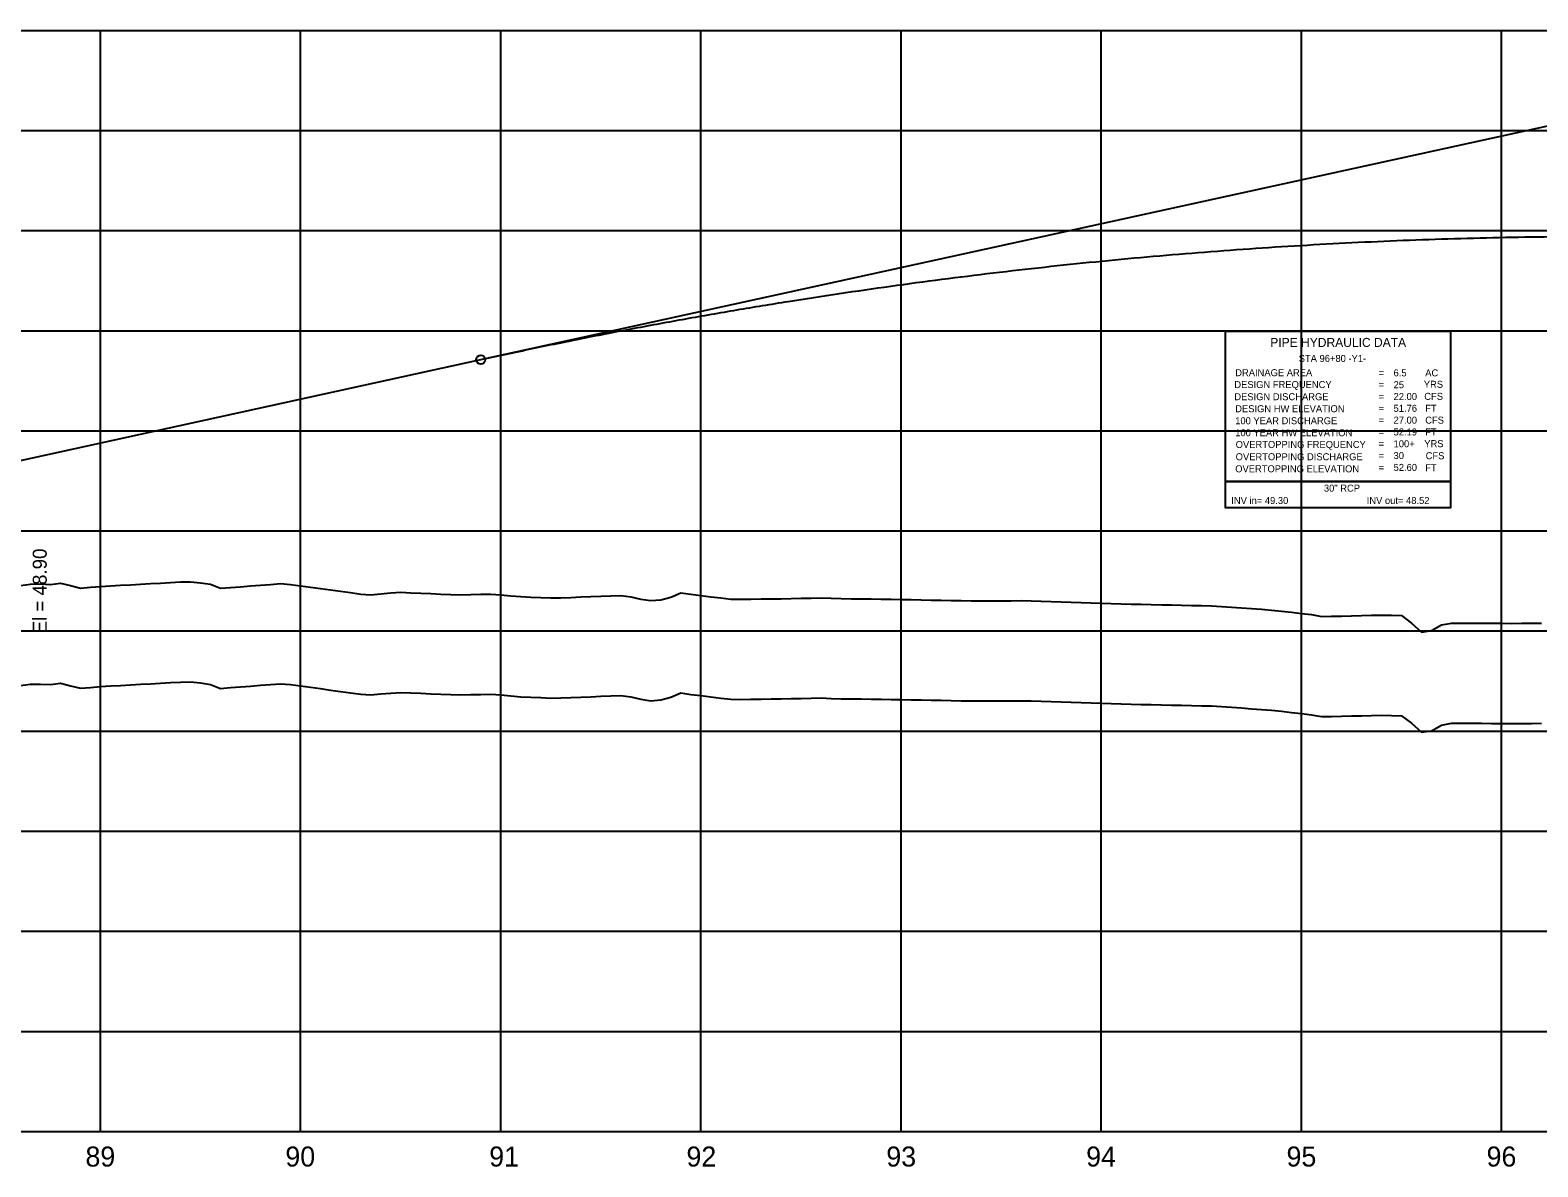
# Model space of a CAD drawing. Extents: x 2345490 to 2436403, y 465165 to 573888.
# Drawn here: x 2389186 to 2389940, y 557766 to 558334 of the extents above; entities that cross this region are included whole.
import ezdxf

# ---------------------------------------------------------------- set-up
doc = ezdxf.new("R2010")
doc.units = 0
for name, color, linetype in [('Old_Level_1', 7, 'Continuous'), ('Old_Level_2', 7, 'Continuous'), ('Old_Level_3', 7, 'Continuous'), ('Old_Level_4', 7, 'Continuous'), ('Old_Level_57', 7, 'Continuous'), ('Old_Level_62', 7, 'Continuous'), ('Old_Level_63', 7, 'Continuous')]:
    doc.layers.add(name, color=color, linetype=linetype)

msp = doc.modelspace()

# ---------------------------------------------------------------- linework, layer by layer
at = {"layer": 'Old_Level_1'}
for points in [[(2389181.5425, 558006.83375), (2389186.5425, 558007.4795), (2389191.5425, 558007.60325), (2389196.5425, 558007.32175), (2389201.5425, 558007.987), (2389206.5425, 558006.761), (2389211.5425, 558005.56825), (2389216.5425, 558005.94675), (2389221.5425, 558006.32525), (2389226.5425, 558006.6745), (2389231.5425, 558006.94825), (2389236.5425, 558007.222), (2389241.5425, 558007.49575), (2389246.5425, 558007.7695), (2389251.5425, 558008.04325), (2389256.5425, 558008.317), (2389261.5425, 558008.58825), (2389266.5425, 558008.64375), (2389271.5425, 558008.23575), (2389276.5425, 558007.4265), (2389281.5425, 558005.44875), (2389286.5425, 558005.836), (2389291.5425, 558006.22325), (2389296.5425, 558006.6105), (2389301.5425, 558006.99775), (2389306.5425, 558007.3845), (2389311.5425, 558007.765), (2389316.5425, 558007.39975), (2389321.5425, 558006.70825)], [(2389321.5425, 558006.70825), (2389326.5425, 558006.01675), (2389331.5425, 558005.32525), (2389336.5425, 558004.63375), (2389341.5425, 558003.942), (2389346.5425, 558003.2505), (2389351.5425, 558002.559), (2389356.5425, 558002.23), (2389361.5425, 558002.66475), (2389366.5425, 558003.0995), (2389371.5425, 558003.452), (2389376.5425, 558003.224), (2389381.5425, 558002.99575), (2389386.5425, 558002.7675), (2389391.5425, 558002.5395), (2389396.5425, 558002.31125), (2389401.5425, 558002.15925), (2389406.5425, 558002.37775), (2389411.5425, 558002.449), (2389416.5425, 558002.52025), (2389421.5425, 558002.22925), (2389426.5425, 558001.71875), (2389431.5425, 558001.29225), (2389436.5425, 558001.06275), (2389441.5425, 558000.8335), (2389446.5425, 558000.604), (2389451.5425, 558000.64475), (2389456.5425, 558000.89975), (2389461.5425, 558001.09525), (2389466.5425, 558001.291), (2389471.5425, 558001.4865), (2389476.5425, 558001.682), (2389481.5425, 558001.87775), (2389486.5425, 558001.20975), (2389491.5425, 557999.98425), (2389496.5425, 557999.304), (2389501.5425, 557999.6535), (2389506.5425, 558001.0615), (2389511.5425, 558003.237), (2389516.5425, 558002.43), (2389521.5425, 558001.827), (2389526.5425, 558001.22375), (2389531.5425, 558000.62075), (2389536.5425, 558000.0175), (2389541.5425, 557999.96125), (2389546.5425, 558000.05), (2389551.5425, 558000.11375), (2389556.5425, 558000.1775), (2389561.5425, 558000.2415), (2389566.5425, 558000.3385), (2389571.5425, 558000.453), (2389576.5425, 558000.5675), (2389581.5425, 558000.67825), (2389586.5425, 558000.446), (2389591.5425, 558000.2805), (2389596.5425, 558000.238), (2389601.5425, 558000.1955), (2389606.5425, 558000.11675), (2389611.5425, 558000.02675), (2389616.5425, 557999.937), (2389621.5425, 557999.847), (2389626.5425, 557999.757), (2389631.5425, 557999.667), (2389636.5425, 557999.577), (2389641.5425, 557999.487), (2389646.5425, 557999.397), (2389651.5425, 557999.307), (2389656.5425, 557999.217), (2389661.5425, 557999.226), (2389666.5425, 557999.23525), (2389671.5425, 557999.2445), (2389676.5425, 557999.25375), (2389681.5425, 557999.263), (2389686.5425, 557999.17775), (2389691.5425, 557999.00875), (2389696.5425, 557998.83975), (2389701.5425, 557998.67075), (2389706.5425, 557998.50175), (2389711.5425, 557998.33275), (2389716.5425, 557998.16375), (2389721.5425, 557997.99475), (2389726.5425, 557997.82575), (2389731.5425, 557997.66125), (2389736.5425, 557997.548), (2389741.5425, 557997.4365), (2389746.5425, 557997.325), (2389751.5425, 557997.21375), (2389756.5425, 557997.10225), (2389761.5425, 557996.99075), (2389766.5425, 557996.8795), (2389771.5425, 557996.768), (2389776.5425, 557996.65675), (2389781.5425, 557996.39), (2389786.5425, 557996.02925), (2389791.5425, 557995.6685), (2389796.5425, 557995.30775), (2389801.5425, 557994.947), (2389806.5425, 557994.58625), (2389811.5425, 557994.03675), (2389816.5425, 557993.48175), (2389821.5425, 557992.92675)], [(2389821.5425, 557992.92675), (2389826.5425, 557992.31125), (2389831.5425, 557991.4145), (2389836.5425, 557991.436), (2389841.5425, 557991.561), (2389846.5425, 557991.686), (2389851.5425, 557991.811), (2389856.5425, 557991.93575), (2389861.5425, 557992.06075), (2389866.5425, 557991.93975), (2389871.5425, 557991.81), (2389876.5425, 557988.07675), (2389881.5425, 557983.58525), (2389886.5425, 557984.2855), (2389891.5425, 557987.15425), (2389896.5425, 557988.0095), (2389901.5425, 557988.03675), (2389906.5425, 557988.0545), (2389911.5425, 557988.00425), (2389916.5425, 557987.94775), (2389921.5425, 557987.933), (2389926.5425, 557987.9295), (2389931.5425, 557987.9445), (2389936.5425, 557987.97075), (2389941.5425, 557987.997)]]:
    msp.add_lwpolyline(points, dxfattribs=at)
at = {"layer": 'Old_Level_2'}
for p, q in [((2389411.5425, 558169.65525), (2390048.8565, 558309.32425)), ((2389121.5425, 558106.101), (2389411.5425, 558169.65525))]:
    msp.add_line(p, q, dxfattribs=at)
msp.add_circle((2389411.5425, 558169.65525), 2.25, dxfattribs=at)
msp.add_spline([(2389411.5425, 558169.65525), (2389437.1425, 558175.13775), (2389462.7425, 558180.36475), (2389488.3425, 558185.336), (2389513.9425, 558190.052), (2389539.5425, 558194.51225), (2389565.1425, 558198.717), (2389590.7425, 558202.666), (2389616.3425, 558206.3595), (2389641.9425, 558209.7975), (2389667.5425, 558212.98), (2389693.1425, 558215.90675), (2389718.7425, 558218.57825), (2389744.3425, 558220.994), (2389769.9425, 558223.154), (2389795.5425, 558225.05875), (2389821.1425, 558226.70775), (2389846.7425, 558228.10125), (2389872.3425, 558229.239), (2389897.9425, 558230.12125), (2389923.5425, 558230.74825), (2389949.1425, 558231.11925), (2389974.7425, 558231.235), (2390000.3425, 558231.095), (2390025.9425, 558230.6995), (2390051.5425, 558230.0485), (2390077.1425, 558229.14175), (2390102.7425, 558227.97975), (2390128.3425, 558226.562), (2390153.9425, 558224.8885), (2390179.5425, 558222.95975), (2390205.1425, 558220.77525), (2390230.7425, 558218.33525), (2390256.3425, 558215.6395), (2390281.9425, 558212.6885), (2390307.5425, 558209.48175), (2390333.1425, 558206.0195), (2390358.7425, 558202.3015), (2390384.3425, 558198.328), (2390409.9425, 558194.09925), (2390435.5425, 558189.6145), (2390461.1425, 558184.8745), (2390486.7425, 558179.87875), (2390512.3425, 558174.6275), (2390537.94275, 558169.12075), (2390563.54275, 558163.35825), (2390589.14275, 558157.34025), (2390614.74275, 558151.06675), (2390640.34275, 558144.53775), (2390665.94275, 558137.753), (2390691.54275, 558130.713)], degree=3, dxfattribs=at)
at = {"layer": 'Old_Level_4'}
for p, q in [((2389783.55325, 558183.8278), (2389896.05325, 558183.8278)), ((2389783.55325, 558108.8278), (2389783.55325, 558183.8278)), ((2389896.05325, 558183.8278), (2389896.05325, 558108.8278)), ((2389896.05325, 558108.8278), (2389783.55325, 558108.8278))]:
    msp.add_line(p, q, dxfattribs=at)
msp.add_lwpolyline([(2389783.55325, 558108.8278), (2389896.05325, 558108.8278), (2389896.05325, 558095.6128), (2389783.55325, 558095.6128)], close=True, dxfattribs=at)
at = {"layer": 'Old_Level_57'}
for p, q in [((2381271.54275, 558334.11325), (2393041.55275, 558334.11325)), ((2389221.54225, 557784.21325), (2389221.54225, 558334.21325)), ((2389221.54225, 557784.11325), (2389221.54225, 558334.11325)), ((2389321.54225, 557784.21325), (2389321.54225, 558334.21325)), ((2389321.54225, 557784.11325), (2389321.54225, 558334.11325)), ((2389421.54225, 557784.21325), (2389421.54225, 558334.21325)), ((2389421.54225, 557784.11325), (2389421.54225, 558334.11325)), ((2389521.54225, 557784.21325), (2389521.54225, 558334.21325)), ((2389521.54225, 557784.11325), (2389521.54225, 558334.11325)), ((2389621.54225, 557784.21325), (2389621.54225, 558334.21325)), ((2389621.54225, 557784.11325), (2389621.54225, 558334.11325)), ((2389721.54225, 557784.21325), (2389721.54225, 558334.21325)), ((2389721.54225, 557784.11325), (2389721.54225, 558334.11325)), ((2389821.54225, 557784.21325), (2389821.54225, 558334.21325)), ((2389821.54225, 557784.11325), (2389821.54225, 558334.11325)), ((2389921.54225, 557784.21325), (2389921.54225, 558334.21325)), ((2389921.54225, 557784.11325), (2389921.54225, 558334.11325)), ((2381271.54275, 558284.11325), (2393041.55275, 558284.11325)), ((2381271.54275, 558234.11325), (2393041.55275, 558234.11325)), ((2381271.54275, 558184.11325), (2393041.55275, 558184.11325)), ((2381271.54275, 558134.11325), (2393041.55275, 558134.11325)), ((2381271.54275, 558084.11325), (2393041.55275, 558084.11325)), ((2381271.5425, 558034.11325), (2393041.55275, 558034.11325)), ((2381271.54275, 557984.11325), (2393041.55275, 557984.11325)), ((2381271.5425, 557934.11325), (2393041.55275, 557934.11325)), ((2381271.54275, 557884.11325), (2393041.55275, 557884.11325)), ((2381271.5425, 557834.11325), (2393041.55275, 557834.11325)), ((2381271.54275, 557784.11325), (2393041.55275, 557784.11325))]:
    msp.add_line(p, q, dxfattribs=at)
at = {"layer": 'Old_Level_62'}
for points in [[(2389181.5425, 558056.83975), (2389186.5425, 558057.4855), (2389191.5425, 558057.60925), (2389196.5425, 558057.32775), (2389201.5425, 558057.993), (2389206.5425, 558056.767), (2389211.5425, 558055.57425), (2389216.5425, 558055.95275), (2389221.5425, 558056.33125), (2389226.5425, 558056.6805), (2389231.5425, 558056.95425), (2389236.5425, 558057.228), (2389241.5425, 558057.50175), (2389246.5425, 558057.7755), (2389251.5425, 558058.04925), (2389256.5425, 558058.323), (2389261.5425, 558058.59425), (2389266.5425, 558058.64975), (2389271.5425, 558058.24175), (2389276.5425, 558057.4325), (2389281.5425, 558055.45475), (2389286.5425, 558055.842), (2389291.5425, 558056.22925), (2389296.5425, 558056.6165), (2389301.5425, 558057.00375), (2389306.5425, 558057.3905), (2389311.5425, 558057.771), (2389316.5425, 558057.40575), (2389321.5425, 558056.71425)], [(2389321.5425, 558056.71425), (2389326.5425, 558056.02275), (2389331.5425, 558055.33125), (2389336.5425, 558054.63975), (2389341.5425, 558053.948), (2389346.5425, 558053.2565), (2389351.5425, 558052.565), (2389356.5425, 558052.236), (2389361.5425, 558052.67075), (2389366.5425, 558053.1055), (2389371.5425, 558053.458), (2389376.5425, 558053.23), (2389381.5425, 558053.00175), (2389386.5425, 558052.7735), (2389391.5425, 558052.5455), (2389396.5425, 558052.31725), (2389401.5425, 558052.16525), (2389406.5425, 558052.38375), (2389411.5425, 558052.455), (2389416.5425, 558052.52625), (2389421.5425, 558052.23525), (2389426.5425, 558051.72475), (2389431.5425, 558051.29825), (2389436.5425, 558051.06875), (2389441.5425, 558050.8395), (2389446.5425, 558050.61), (2389451.5425, 558050.65075), (2389456.5425, 558050.90575), (2389461.5425, 558051.10125), (2389466.5425, 558051.297), (2389471.5425, 558051.4925), (2389476.5425, 558051.688), (2389481.5425, 558051.88375), (2389486.5425, 558051.21575), (2389491.5425, 558049.99025), (2389496.5425, 558049.31), (2389501.5425, 558049.6595), (2389506.5425, 558051.0675), (2389511.5425, 558053.243), (2389516.5425, 558052.436), (2389521.5425, 558051.833), (2389526.5425, 558051.22975), (2389531.5425, 558050.62675), (2389536.5425, 558050.0235), (2389541.5425, 558049.96725), (2389546.5425, 558050.056), (2389551.5425, 558050.11975), (2389556.5425, 558050.1835), (2389561.5425, 558050.2475), (2389566.5425, 558050.3445), (2389571.5425, 558050.459), (2389576.5425, 558050.5735), (2389581.5425, 558050.68425), (2389586.5425, 558050.452), (2389591.5425, 558050.2865), (2389596.5425, 558050.244), (2389601.5425, 558050.2015), (2389606.5425, 558050.12275), (2389611.5425, 558050.03275), (2389616.5425, 558049.943), (2389621.5425, 558049.853), (2389626.5425, 558049.763), (2389631.5425, 558049.673), (2389636.5425, 558049.583), (2389641.5425, 558049.493), (2389646.5425, 558049.403), (2389651.5425, 558049.313), (2389656.5425, 558049.223), (2389661.5425, 558049.232), (2389666.5425, 558049.24125), (2389671.5425, 558049.2505), (2389676.5425, 558049.25975), (2389681.5425, 558049.269), (2389686.5425, 558049.18375), (2389691.5425, 558049.01475), (2389696.5425, 558048.84575), (2389701.5425, 558048.67675), (2389706.5425, 558048.50775), (2389711.5425, 558048.33875), (2389716.5425, 558048.16975), (2389721.5425, 558048.00075), (2389726.5425, 558047.83175), (2389731.5425, 558047.66725), (2389736.5425, 558047.554), (2389741.5425, 558047.4425), (2389746.5425, 558047.331), (2389751.5425, 558047.21975), (2389756.5425, 558047.10825), (2389761.5425, 558046.99675), (2389766.5425, 558046.8855), (2389771.5425, 558046.774), (2389776.5425, 558046.66275), (2389781.5425, 558046.396), (2389786.5425, 558046.03525), (2389791.5425, 558045.6745), (2389796.5425, 558045.31375), (2389801.5425, 558044.953), (2389806.5425, 558044.59225), (2389811.5425, 558044.04275), (2389816.5425, 558043.48775), (2389821.5425, 558042.93275)], [(2389821.5425, 558042.93275), (2389826.5425, 558042.31725), (2389831.5425, 558041.4205), (2389836.5425, 558041.442), (2389841.5425, 558041.567), (2389846.5425, 558041.692), (2389851.5425, 558041.817), (2389856.5425, 558041.94175), (2389861.5425, 558042.06675), (2389866.5425, 558041.94575), (2389871.5425, 558041.816), (2389876.5425, 558038.08275), (2389881.5425, 558033.59125), (2389886.5425, 558034.2915), (2389891.5425, 558037.16025), (2389896.5425, 558038.0155), (2389901.5425, 558038.04275), (2389906.5425, 558038.0605), (2389911.5425, 558038.01025), (2389916.5425, 558037.95375), (2389921.5425, 558037.939), (2389926.5425, 558037.9355), (2389931.5425, 558037.9505), (2389936.5425, 558037.97675), (2389941.5425, 558038.003)]]:
    msp.add_lwpolyline(points, dxfattribs=at)
at = {"layer": 'Old_Level_63'}
msp.add_line((2381321.5425, 557784.113), (2393019.104, 557784.113), dxfattribs=at)

# ---------------------------------------------------------------- texts
at = {"layer": 'Old_Level_1'}
for s, p in [('89', (2389214.053, 557766.613)), ('90', (2389313.929, 557766.613)), ('91', (2389415.7685, 557766.613)), ('92', (2389514.31675, 557766.613)), ('93', (2389614.1515, 557766.613)), ('94', (2389713.994, 557766.613)), ('95', (2389814.0865, 557766.613)), ('96', (2389914.0275, 557766.613))]:
    msp.add_text(s, height=10.000001, dxfattribs=at).set_placement(p)
at = {"layer": 'Old_Level_3'}
msp.add_text('El = 48.90', height=7.000001, rotation=90, dxfattribs=at).set_placement((2389194.6987, 558032.88674))
at = {"layer": 'Old_Level_4'}
for s, height, p in [('PIPE HYDRAULIC DATA', 4.49985, (2389805.95325, 558176.0028)), ('STA 96+80 -Y1-', 3.4998, (2389820.174, 558168.5023)), ('DESIGN FREQUENCY', 3.49995, (2389788.00325, 558155.4528)), ('DRAINAGE AREA', 3.49995, (2389788.45325, 558161.3778)), ('=        ', 3.49995, (2389860.10325, 558161.2778)), ('25', 3.49995, (2389867.56375, 558155.3773)), ('6.5', 3.49995, (2389867.56375, 558161.2773)), ('YRS', 3.49995, (2389882.67825, 558155.5778)), ('AC', 3.49995, (2389883.37825, 558161.2778)), ('DESIGN DISCHARGE', 3.49995, (2389788.00325, 558149.3778)), ('=        ', 3.49995, (2389860.10325, 558155.3778)), ('=        ', 3.49995, (2389860.10325, 558149.4778)), ('22.00', 3.49995, (2389867.56375, 558149.4773)), ('CFS', 3.49995, (2389882.90325, 558149.5528)), ('DESIGN HW ELEVATION', 3.49995, (2389788.45325, 558143.3778)), ('=        ', 3.49995, (2389860.10325, 558143.5778)), ('51.76', 3.49995, (2389867.56375, 558143.5773)), ('FT', 3.49995, (2389883.37825, 558143.5778)), ('100 YEAR DISCHARGE', 3.49995, (2389788.45325, 558137.3778)), ('=        ', 3.49995, (2389860.10325, 558137.6778)), ('27.00', 3.49995, (2389867.56375, 558137.6773)), ('CFS', 3.49995, (2389883.37825, 558137.6778)), ('100 YEAR HW ELEVATION', 3.49995, (2389788.45325, 558131.3778)), ('OVERTOPPING FREQUENCY', 3.49995, (2389788.67825, 558125.5278)), ('=        ', 3.49995, (2389860.10325, 558131.7778)), ('=        ', 3.49995, (2389860.10325, 558125.8778)), ('52.19', 3.49995, (2389867.56375, 558131.77755)), ('100+', 3.49995, (2389867.56375, 558125.87755)), ('YRS', 3.49995, (2389882.90325, 558125.9278)), ('FT', 3.49995, (2389883.37825, 558131.7778)), ('OVERTOPPING DISCHARGE', 3.49995, (2389788.67825, 558119.4028)), ('=        ', 3.49995, (2389860.10325, 558119.9778)), ('30', 3.49995, (2389867.56375, 558119.97755)), ('CFS', 3.49995, (2389883.60325, 558119.9028)), ('OVERTOPPING ELEVATION', 3.49995, (2389788.45325, 558113.3778)), ('=        ', 3.49995, (2389860.10325, 558114.0778)), ('52.60', 3.49995, (2389867.56375, 558114.07755)), ('FT', 3.49995, (2389883.37825, 558113.8778)), ('30" RCP', 3.4998, (2389832.759, 558103.72555)), ('INV in= 49.30', 3.4998, (2389786.48575, 558097.5398)), ('INV out= 48.52', 3.4998, (2389854.1625, 558097.5398))]:
    msp.add_text(s, height=height, dxfattribs=at).set_placement(p)

doc.saveas('drawing.dxf')
